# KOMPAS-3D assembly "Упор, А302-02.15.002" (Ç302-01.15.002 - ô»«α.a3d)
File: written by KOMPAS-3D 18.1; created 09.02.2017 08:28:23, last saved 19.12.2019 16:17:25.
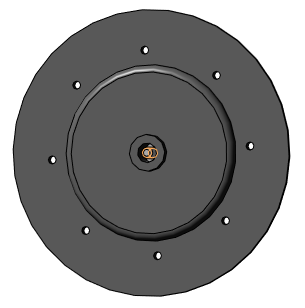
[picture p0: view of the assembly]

Document properties: Автор: Милов; Организация: Милов; Полное имя файла: А302-01.15.002 - Упор.a3d

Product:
- Part/product: Упор  | designation А302-02.15.002
    Материал: Сталь 12Х18Н10Т ГОСТ 5632-72 (density 7900 kg/m3)
    Масса: 1.61349
    Раздел спецификации: Детали
    Форматы листов документа: A3
    source file: А302-02.00.000 - ASTRA-302 (МЭ200)\А302-02.15.002 - Упор.cdw
  - Body: Тело 10
      Масса: 1.59645
  - Component [standard]: Болт с шестигранной головкой с фланцем ГОСТ Р 55739-М8 x 16-A2-70  | pos. 47  | Масса: 0.0170379; Раздел спецификации: Стандартные изделия; Рассекать на разрезах: no; additional columns: ГОСТ Р 55739-2013; М8 x 16 - A2-70; Нержавеющая сталь; source file: C:\Program Files\ASCON\KOMPAS-3D v18\Libs\PartLib\DATA\VAULT\methods\kompas\3d\PLib_Bolt_1_ISO_1100.m3d
- Part/product: Упор  | designation А302-01.15.002
    Масса: 0.395725
    Раздел спецификации: Детали
    Форматы листов документа: A3
- Part/product: Упор  | designation А302-04.15.002
    Материал: Сталь 12Х18Н10Т ГОСТ 5632-72 (density 7900 kg/m3)
    Масса: 1.61349
    Раздел спецификации: Детали
    Форматы листов документа: A3
    source file: ..\А302-04.00.000 - Мембранный насос ASTRA-302-PP\А302-04.15.002 - Упор.cdw
  - Body: Тело 10
      Масса: 1.59645

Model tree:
1. Эскиз:7
2. Операция вращения:1
     Угол 1 = 360
3. Скругление:18
     Радиус = 6
4. Скругление:19
     Радиус = 2
5. Эскиз:20
6. Вырезать элемент выдавливания:1
     Расстояние 1 = 15
7. Эскиз:21
8. Вырезать элемент выдавливания:2
     Расстояние 1 = 7.5
9. Массив по концентрической сетке:1  (with: Вырезать элемент выдавливания:1, Эскиз:20, Вырезать элемент выдавливания:2, Эскиз:21)  (labels: v2239_h1)  (6 pattern instances)
     Шаг 2 = 360
10. Массив по концентрической сетке:2  (2 pattern instances)
11. Вырезать элемент выдавливания:1  (with: Эскиз:20)  (6 pattern instances)
     N 1 = 1; Шаг 1 = 10; Шаг 2 = 360; Номер 1 = 1
12. Скругление:20  (with: Операция вращения:1)  (labels: Сталь 12Х18Н10Т ГОСТ 5632-72)
     Радиус = 5

Expressions: 250/2; (250-60)/2; (250-60)/2+12; 13.5/2; 195/2; 25/2
Referenced files in C:\Program Files\ASCON\KOMPAS-3D v18\Libs\PartLib\DATA\VAULT\methods\kompas\3d\: PLib_Bolt_1_ISO_1100.m3d
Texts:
  hole1
  hole2

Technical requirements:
  Gost Type A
